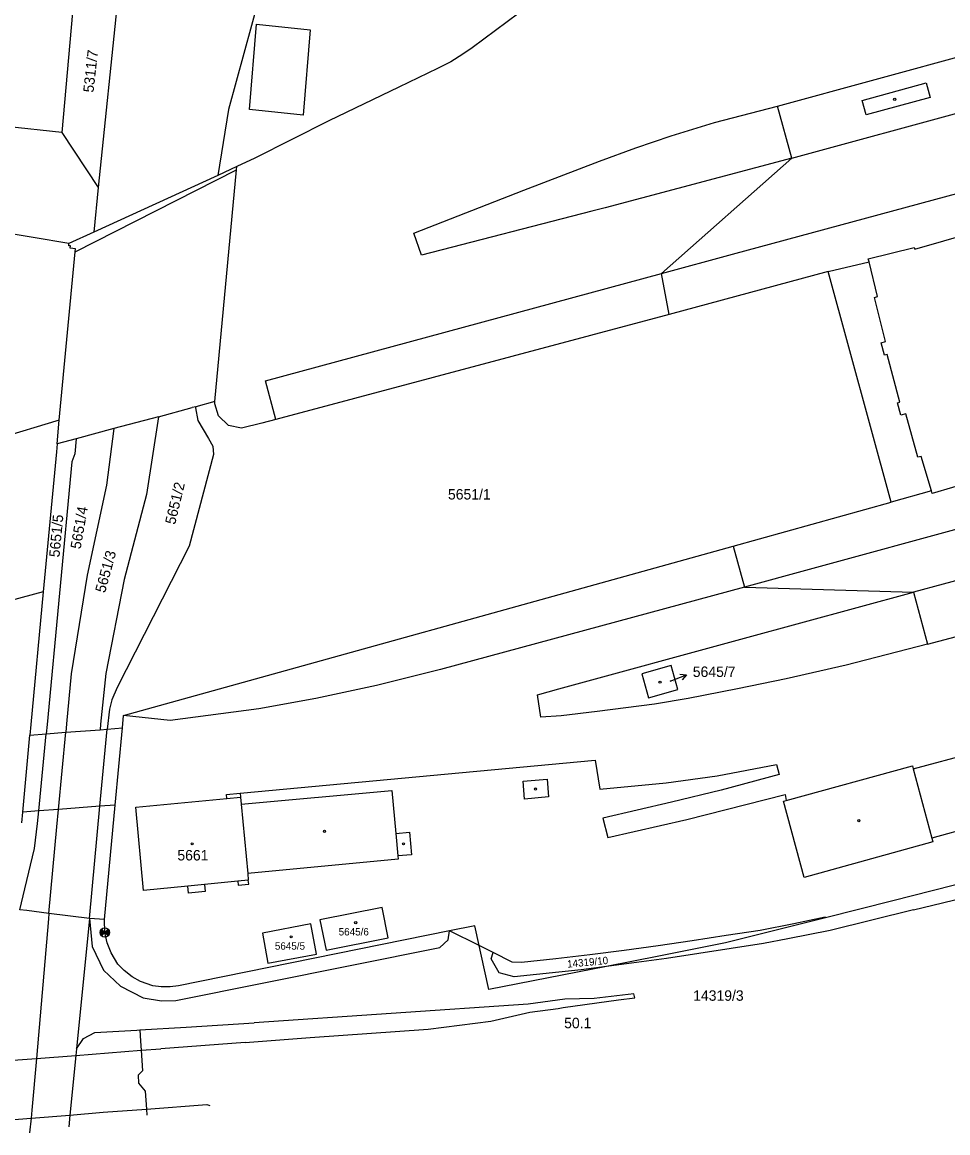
# Model space of a CAD drawing. Extents: x -825057 to -819383, y -1071633 to -1067888.
# Drawn here: x -821893.8 to -821743.3, y -1070405.8 to -1070225.1 of the extents above; entities that cross this region are included whole.
import ezdxf

# ---------------------------------------------------------------- set-up
doc = ezdxf.new("R2010")
doc.units = 0
for name, color, linetype in [('Vrstva 1', 7, 'Continuous'), ('Vrstva 16', 7, 'Continuous'), ('Vrstva 17', 7, 'Continuous'), ('Vrstva 18', 7, 'Continuous'), ('Vrstva 19', 7, 'Continuous'), ('Vrstva 24', 7, 'Continuous'), ('Vrstva 25', 7, 'Continuous'), ('Vrstva 4', 7, 'Continuous')]:
    doc.layers.add(name, color=color, linetype=linetype)

msp = doc.modelspace()

# ---------------------------------------------------------------- linework, layer by layer
at = {"layer": 'Vrstva 1'}
for p, q in [((-821770.97, -1070238.79), (-821656.22, -1070207.49)), ((-821853.88, -1070215.88), (-821860.28, -1070239.36)), ((-821885.09, -1070217.04), (-821887.37, -1070243.06)), ((-821877.85, -1070216.96), (-821881.44, -1070252.03)), ((-821811.14, -1070222.26), (-821820.66, -1070229.3)), ((-821822.14, -1070230.34), (-821824.13, -1070231.61)), ((-821820.66, -1070229.3), (-821822.14, -1070230.34)), ((-821824.13, -1070231.61), (-821826.3, -1070232.65)), ((-821826.3, -1070232.65), (-821832.57, -1070235.71)), ((-821832.57, -1070235.71), (-821843.93, -1070241.18)), ((-821860.28, -1070239.36), (-821862.02, -1070250.06)), ((-821768.65, -1070247.26), (-821770.97, -1070238.79)), ((-821843.93, -1070241.18), (-821856.01, -1070247.24)), ((-821887.37, -1070243.06), (-821881.44, -1070252.03)), ((-821858.9, -1070248.63), (-821862.02, -1070250.06)), ((-821856.01, -1070247.24), (-821858.9, -1070248.63)), ((-821789.86, -1070266.02), (-821768.65, -1070247.26)), ((-821862.02, -1070250.06), (-821882.18, -1070259.28)), ((-821881.44, -1070252.03), (-821882.18, -1070259.28)), ((-821886.25, -1070261.14), (-821912.61, -1070256.71)), ((-821882.18, -1070259.28), (-821886.25, -1070261.14)), ((-821886.26, -1070261.49), (-821886.25, -1070261.14)), ((-821887.79, -1070289.89), (-821885.23, -1070262.51)), ((-821885.97, -1070261.52), (-821886.26, -1070261.49)), ((-821886, -1070261.88), (-821885.97, -1070261.52)), ((-821885.18, -1070262.01), (-821886, -1070261.88)), ((-821885.23, -1070262.51), (-821885.18, -1070262.01)), ((-821788.6, -1070272.7), (-821789.86, -1070266.02)), ((-821762.72, -1070265.7), (-821788.6, -1070272.7)), ((-821752.47, -1070303.19), (-821762.72, -1070265.7)), ((-821788.6, -1070272.7), (-821852.55, -1070289.75)), ((-821871.65, -1070289.3), (-821866.18, -1070287.83)), ((-821865.59, -1070287.68), (-821866.18, -1070287.83)), ((-821865.59, -1070287.68), (-821865.61, -1070287.86)), ((-821865.61, -1070287.86), (-821865.28, -1070289.91)), ((-821862.47, -1070286.84), (-821865.59, -1070287.68)), ((-821862.5, -1070287.2), (-821862.47, -1070286.84)), ((-821861.91, -1070289.16), (-821862.5, -1070287.2)), ((-821887.79, -1070289.89), (-822065.38, -1070343.33)), ((-821888.15, -1070293.72), (-821887.79, -1070289.89)), ((-821871.65, -1070289.3), (-821878.9, -1070291.24)), ((-821871.65, -1070289.3), (-821873.61, -1070301.98)), ((-821865.28, -1070289.91), (-821863.52, -1070292.87)), ((-821860.28, -1070290.72), (-821861.91, -1070289.16)), ((-821852.55, -1070289.75), (-821854.87, -1070290.38)), ((-821878.9, -1070291.24), (-821885.02, -1070292.88)), ((-821878.9, -1070291.24), (-821880.11, -1070300.43)), ((-821858.13, -1070291.19), (-821860.28, -1070290.72)), ((-821854.87, -1070290.38), (-821858.13, -1070291.19)), ((-821888.15, -1070293.72), (-821888.27, -1070294.99)), ((-821885.02, -1070292.88), (-821888.15, -1070293.72)), ((-821885.02, -1070292.88), (-821885.27, -1070295.32)), ((-821863.52, -1070292.87), (-821862.8, -1070294.08)), ((-821888.27, -1070294.99), (-821890.39, -1070317.77)), ((-821885.27, -1070295.32), (-821885.77, -1070296.62)), ((-821862.71, -1070295.46), (-821866.67, -1070310.37)), ((-821862.8, -1070294.08), (-821862.71, -1070295.46)), ((-821885.77, -1070296.62), (-821889.78, -1070339.38)), ((-821880.11, -1070300.43), (-821883.28, -1070315.06)), ((-821873.61, -1070301.98), (-821877.22, -1070315.8)), ((-821778.17, -1070310.34), (-821752.47, -1070303.19)), ((-821866.67, -1070310.37), (-821878.38, -1070333.34)), ((-821877.32, -1070337.92), (-821778.17, -1070310.34)), ((-821778.17, -1070310.34), (-821776.32, -1070317)), ((-821883.28, -1070315.06), (-821885.88, -1070331.13)), ((-821877.22, -1070315.8), (-821880.24, -1070331.05)), ((-821776.32, -1070317), (-821748.88, -1070317.82)), ((-821890.39, -1070317.77), (-821915.8, -1070324.55)), ((-821890.39, -1070317.77), (-821892.42, -1070339.38)), ((-821748.88, -1070317.82), (-821746.56, -1070326.32)), ((-821746.56, -1070326.32), (-821720.29, -1070319.13)), ((-821788.26, -1070329.77), (-821793.05, -1070331.11)), ((-821787.18, -1070333.68), (-821788.26, -1070329.77)), ((-821885.88, -1070331.13), (-821886.6, -1070339.25)), ((-821880.24, -1070331.05), (-821881.06, -1070339.29)), ((-821793.05, -1070331.11), (-821791.97, -1070335.01)), ((-821878.38, -1070333.34), (-821879.27, -1070335.33)), ((-821791.97, -1070335.01), (-821787.18, -1070333.68)), ((-821879.6, -1070336.88), (-821880.02, -1070340.11)), ((-821879.27, -1070335.33), (-821879.6, -1070336.88)), ((-821877.51, -1070339.92), (-821877.32, -1070337.92)), ((-821748.92, -1070346.58), (-821715.23, -1070337.53)), ((-821892.42, -1070339.38), (-821892.57, -1070341.07)), ((-821889.78, -1070339.38), (-821889.92, -1070340.87)), ((-821889.92, -1070340.87), (-821886.73, -1070340.62)), ((-821886.6, -1070339.25), (-821886.73, -1070340.62)), ((-821886.73, -1070340.62), (-821881.14, -1070340.2)), ((-821881.06, -1070339.29), (-821881.14, -1070340.2)), ((-821881.14, -1070340.2), (-821880.02, -1070340.11)), ((-821880.02, -1070340.11), (-821877.51, -1070339.92)), ((-821893.74, -1070353.62), (-821892.57, -1070341.07)), ((-821892.57, -1070341.07), (-821889.92, -1070340.87)), ((-821769.57, -1070351.7), (-821749.05, -1070346.07)), ((-821749.05, -1070346.07), (-821748.92, -1070346.58)), ((-821712.35, -1070348.43), (-821745.89, -1070357.86)), ((-821875.36, -1070352.81), (-821860.52, -1070351.39)), ((-821860.52, -1070351.39), (-821858.31, -1070351.18)), ((-821858.31, -1070351.18), (-821858.2, -1070352.34)), ((-821858.2, -1070352.34), (-821833.72, -1070350.1)), ((-821833.72, -1070350.1), (-821833.07, -1070357.07)), ((-821874.08, -1070366.34), (-821875.36, -1070352.81)), ((-821769.98, -1070351.81), (-821769.57, -1070351.7)), ((-821766.66, -1070364.26), (-821769.98, -1070351.81)), ((-821893.9, -1070355.33), (-821893.74, -1070353.62)), ((-821833.07, -1070357.07), (-821830.82, -1070356.88)), ((-821830.82, -1070356.88), (-821830.5, -1070360.54)), ((-821745.74, -1070358.44), (-821766.66, -1070364.26)), ((-821745.89, -1070357.86), (-821745.74, -1070358.44)), ((-821830.5, -1070360.54), (-821832.73, -1070360.73)), ((-821832.68, -1070361.28), (-821857.15, -1070363.57)), ((-821832.73, -1070360.73), (-821832.68, -1070361.28)), ((-821724.98, -1070361.04), (-821752.21, -1070368.06)), ((-821857.15, -1070363.57), (-821857.05, -1070364.68)), ((-821866.87, -1070365.63), (-821874.08, -1070366.34)), ((-821866.76, -1070366.78), (-821866.87, -1070365.63)), ((-821858.73, -1070364.84), (-821864.19, -1070365.37)), ((-821864.19, -1070365.37), (-821864.08, -1070366.52)), ((-821857.05, -1070364.68), (-821858.73, -1070364.84)), ((-821864.08, -1070366.52), (-821866.76, -1070366.78)), ((-821893.09, -1070369.63), (-821894.23, -1070369.49)), ((-821889.47, -1070370.08), (-821893.09, -1070369.63)), ((-821835.27, -1070369.11), (-821845.4, -1070371.15)), ((-821834.28, -1070374.03), (-821835.27, -1070369.11)), ((-821752.21, -1070368.06), (-821763.16, -1070370.81)), ((-821889.55, -1070370.95), (-821891.51, -1070393.68)), ((-821889.47, -1070370.08), (-821889.55, -1070370.95)), ((-821882.86, -1070370.91), (-821889.47, -1070370.08)), ((-821882.86, -1070370.91), (-821884.99, -1070392.1)), ((-821880.41, -1070371.05), (-821882.86, -1070370.91)), ((-821880.39, -1070373.18), (-821880.41, -1070371.05)), ((-821845.4, -1070371.15), (-821844.41, -1070376.06)), ((-821763.16, -1070370.81), (-821779.44, -1070374.89)), ((-821763.21, -1070370.68), (-821768.35, -1070371.78)), ((-821763.16, -1070370.81), (-821763.21, -1070370.68)), ((-821880, -1070374.86), (-821880.39, -1070373.18)), ((-821824.32, -1070372.91), (-821868.41, -1070381.84)), ((-821846.89, -1070371.77), (-821854.74, -1070373.28)), ((-821845.96, -1070376.71), (-821846.89, -1070371.77)), ((-821820.23, -1070372.08), (-821824.32, -1070372.91)), ((-821819.52, -1070375.3), (-821820.23, -1070372.08)), ((-821773.79, -1070372.85), (-821779.35, -1070373.7)), ((-821768.35, -1070371.78), (-821773.79, -1070372.85)), ((-821879.37, -1070376.51), (-821880, -1070374.86)), ((-821854.74, -1070373.28), (-821853.85, -1070378.19)), ((-821844.41, -1070376.06), (-821834.28, -1070374.03)), ((-821784.88, -1070374.56), (-821790.39, -1070375.37)), ((-821779.44, -1070374.89), (-821790.3, -1070377.03)), ((-821779.35, -1070373.7), (-821784.88, -1070374.56)), ((-821878.26, -1070378.31), (-821879.37, -1070376.51)), ((-821853.85, -1070378.19), (-821845.96, -1070376.71)), ((-821819.24, -1070376.56), (-821819.52, -1070375.3)), ((-821817.21, -1070376.45), (-821819.52, -1070375.3)), ((-821817.94, -1070382.46), (-821819.24, -1070376.56)), ((-821814.12, -1070377.99), (-821817.21, -1070376.45)), ((-821801.48, -1070376.84), (-821807.05, -1070377.47)), ((-821795.92, -1070376.14), (-821801.48, -1070376.84)), ((-821790.39, -1070375.37), (-821795.92, -1070376.14)), ((-821877.22, -1070379.38), (-821878.26, -1070378.31)), ((-821812.62, -1070378.09), (-821814.12, -1070377.99)), ((-821807.05, -1070377.47), (-821812.62, -1070378.09)), ((-821790.3, -1070377.03), (-821798.8, -1070378.7)), ((-821875.96, -1070380.37), (-821877.22, -1070379.38)), ((-821874.56, -1070381.15), (-821875.96, -1070380.37)), ((-821798.8, -1070378.7), (-821817.94, -1070382.46)), ((-821872.57, -1070381.86), (-821874.56, -1070381.15)), ((-821871.2, -1070382.02), (-821872.57, -1070381.86)), ((-821869.74, -1070382.02), (-821871.2, -1070382.02)), ((-821868.41, -1070381.84), (-821869.74, -1070382.02)), ((-821884.99, -1070392.1), (-821885.09, -1070393.18)), ((-821891.51, -1070393.68), (-821892.23, -1070402.09)), ((-821885.09, -1070393.18), (-821886.07, -1070402.87)), ((-821892.23, -1070402.09), (-821892.37, -1070403.39)), ((-821892.37, -1070403.39), (-821892.63, -1070405.76)), ((-821886.07, -1070402.87), (-821886.26, -1070404.8))]:
    msp.add_line(p, q, dxfattribs=at)
at = {"layer": 'Vrstva 16'}
msp.add_line((-821788.45, -1070332.33), (-821785.797, -1070331.289), dxfattribs=at)
msp.add_lwpolyline([(-821786.855, -1070331.194), (-821785.797, -1070331.289), (-821786.508, -1070332.078)], dxfattribs=at)
at = {"layer": 'Vrstva 24'}
for p, q in [((-821881.14, -1070373.18), (-821879.64, -1070373.18)), ((-821881.114, -1070372.986), (-821879.666, -1070373.374)), ((-821881.114, -1070373.374), (-821879.666, -1070372.986)), ((-821881.039, -1070372.805), (-821879.741, -1070373.555)), ((-821881.039, -1070373.555), (-821879.741, -1070372.805)), ((-821880.92, -1070373.71), (-821879.86, -1070372.65)), ((-821880.92, -1070372.65), (-821879.86, -1070373.71))]:
    msp.add_line(p, q, dxfattribs=at)
msp.add_circle((-821880.39, -1070373.18), 0.75, dxfattribs=at)
at = {"layer": 'Vrstva 25'}
for centre in [(-821751.92, -1070237.69), (-821790.08, -1070332.47), (-821810.35, -1070349.85), (-821757.75, -1070355), (-821844.65, -1070356.73), (-821866.17, -1070358.76), (-821831.8, -1070358.77), (-821839.58, -1070371.59), (-821850.08, -1070373.9)]:
    msp.add_circle(centre, 0.175, dxfattribs=at)
at = {"layer": 'Vrstva 4'}
for p, q in [((-821768.65, -1070247.26), (-821655.78, -1070216.48)), ((-821856.88, -1070239.33), (-821855.74, -1070225.48)), ((-821855.74, -1070225.48), (-821847.01, -1070226.39)), ((-821847.01, -1070226.39), (-821848.13, -1070240.26)), ((-821778.29, -1070262.89), (-821655.15, -1070229.56)), ((-821757.21, -1070237.86), (-821746.8, -1070235)), ((-821746.8, -1070235), (-821746.15, -1070237.37)), ((-821746.15, -1070237.37), (-821756.56, -1070240.23)), ((-821848.13, -1070240.26), (-821856.88, -1070239.33)), ((-821781.21, -1070241.47), (-821770.97, -1070238.79)), ((-821756.56, -1070240.23), (-821757.21, -1070237.86)), ((-821887.37, -1070243.06), (-821896.42, -1070242.13)), ((-821788.27, -1070243.61), (-821781.21, -1070241.47)), ((-821794.04, -1070245.6), (-821788.27, -1070243.61)), ((-821799.92, -1070247.74), (-821794.04, -1070245.6)), ((-821858.95, -1070249.13), (-821858.9, -1070248.63)), ((-821812.22, -1070252.44), (-821799.92, -1070247.74)), ((-821768.65, -1070247.26), (-821799, -1070255.31)), ((-821885.23, -1070262.51), (-821858.95, -1070249.13)), ((-821862.47, -1070286.84), (-821858.95, -1070249.13)), ((-821830.12, -1070259.48), (-821812.22, -1070252.44)), ((-821801.15, -1070255.85), (-821828.88, -1070263.02)), ((-821799, -1070255.31), (-821801.15, -1070255.85)), ((-821748.66, -1070262.06), (-821730.49, -1070256.79)), ((-821828.88, -1070263.02), (-821830.12, -1070259.48)), ((-821789.86, -1070266.02), (-821778.29, -1070262.89)), ((-821756.22, -1070263.61), (-821748.73, -1070261.76)), ((-821748.73, -1070261.76), (-821748.66, -1070262.06)), ((-821762.72, -1070265.7), (-821756.09, -1070264.14)), ((-821756.09, -1070264.14), (-821756.22, -1070263.61)), ((-821754.69, -1070269.77), (-821756.09, -1070264.14)), ((-821854.24, -1070283.45), (-821789.86, -1070266.02)), ((-821755.23, -1070269.91), (-821754.69, -1070269.77)), ((-821753.39, -1070277.08), (-821755.23, -1070269.91)), ((-821754.11, -1070277.29), (-821753.39, -1070277.08)), ((-821753.56, -1070279.32), (-821754.11, -1070277.29)), ((-821753.17, -1070279.21), (-821753.56, -1070279.32)), ((-821751.06, -1070286.93), (-821753.17, -1070279.21)), ((-821852.55, -1070289.75), (-821854.24, -1070283.45)), ((-821751.45, -1070287.03), (-821751.06, -1070286.93)), ((-821750.9, -1070289.06), (-821751.45, -1070287.03)), ((-821750.12, -1070288.84), (-821750.9, -1070289.06)), ((-821748.13, -1070295.9), (-821750.12, -1070288.84)), ((-821747.6, -1070295.75), (-821748.13, -1070295.9)), ((-821745.93, -1070301.37), (-821747.6, -1070295.75)), ((-821738.43, -1070299.58), (-821745.81, -1070301.78)), ((-821745.93, -1070301.37), (-821752.47, -1070303.19)), ((-821745.81, -1070301.78), (-821745.93, -1070301.37)), ((-821724.55, -1070302.91), (-821765.81, -1070314.15)), ((-821722.5, -1070310.7), (-821748.88, -1070317.82)), ((-821765.81, -1070314.15), (-821776.32, -1070317)), ((-821776.32, -1070317), (-821825.8, -1070330.44)), ((-821776.32, -1070325.33), (-821748.88, -1070317.82)), ((-821806.54, -1070333.58), (-821776.32, -1070325.33)), ((-821746.56, -1070326.32), (-821759.83, -1070329.69)), ((-821759.83, -1070329.69), (-821769.58, -1070331.93)), ((-821825.8, -1070330.44), (-821836.19, -1070333.04)), ((-821836.19, -1070333.04), (-821846.09, -1070335.14)), ((-821769.58, -1070331.93), (-821777.49, -1070333.57)), ((-821846.09, -1070335.14), (-821855.36, -1070336.82)), ((-821810.01, -1070334.54), (-821806.54, -1070333.58)), ((-821809.46, -1070338.16), (-821810.01, -1070334.54)), ((-821785.51, -1070335.11), (-821791, -1070336.07)), ((-821777.49, -1070333.57), (-821785.51, -1070335.11)), ((-821855.36, -1070336.82), (-821869.74, -1070338.72)), ((-821791, -1070336.07), (-821800.32, -1070337.26)), ((-821869.74, -1070338.72), (-821877.32, -1070337.92)), ((-821806.14, -1070337.96), (-821809.46, -1070338.16)), ((-821800.32, -1070337.26), (-821806.14, -1070337.96)), ((-821887.92, -1070353.18), (-821886.73, -1070340.62)), ((-821881.18, -1070352.66), (-821880.02, -1070340.11)), ((-821878.68, -1070352.47), (-821877.51, -1070339.92)), ((-821891.12, -1070353.42), (-821889.92, -1070340.87)), ((-821858.38, -1070350.54), (-821800.66, -1070345.18)), ((-821800.66, -1070345.18), (-821799.85, -1070349.9)), ((-821780.79, -1070347.72), (-821771.13, -1070345.89)), ((-821771.13, -1070345.89), (-821770.7, -1070347.48)), ((-821789.1, -1070348.84), (-821780.79, -1070347.72)), ((-821770.7, -1070347.48), (-821780.16, -1070350.02)), ((-821748.92, -1070346.58), (-821745.89, -1070357.86)), ((-821812.37, -1070348.6), (-821808.46, -1070348.24)), ((-821812.11, -1070351.49), (-821812.37, -1070348.6)), ((-821808.46, -1070348.24), (-821808.2, -1070351.13)), ((-821799.85, -1070349.9), (-821789.1, -1070348.84)), ((-821860.59, -1070350.75), (-821858.38, -1070350.54)), ((-821860.52, -1070351.39), (-821860.59, -1070350.75)), ((-821858.38, -1070350.54), (-821858.31, -1070351.18)), ((-821808.2, -1070351.13), (-821812.11, -1070351.49)), ((-821780.16, -1070350.02), (-821788.24, -1070351.98)), ((-821785.71, -1070354.82), (-821769.76, -1070350.74)), ((-821769.76, -1070350.74), (-821769.57, -1070351.7)), ((-821887.92, -1070353.18), (-821891.12, -1070353.42)), ((-821888.19, -1070356.02), (-821887.92, -1070353.18)), ((-821881.18, -1070352.66), (-821887.92, -1070353.18)), ((-821882.86, -1070370.91), (-821881.18, -1070352.66)), ((-821878.68, -1070352.47), (-821881.18, -1070352.66)), ((-821880.41, -1070371.05), (-821878.68, -1070352.47)), ((-821858.2, -1070352.34), (-821857.15, -1070363.57)), ((-821788.24, -1070351.98), (-821799.39, -1070354.58)), ((-821891.12, -1070353.42), (-821893.74, -1070353.62)), ((-821891.32, -1070355.46), (-821891.12, -1070353.42)), ((-821799.39, -1070354.58), (-821798.57, -1070357.76)), ((-821798.57, -1070357.76), (-821785.71, -1070354.82)), ((-821891.8, -1070359.51), (-821891.32, -1070355.46)), ((-821889.47, -1070370.08), (-821888.19, -1070356.02)), ((-821833.07, -1070357.07), (-821832.73, -1070360.73)), ((-821893.38, -1070366.1), (-821891.8, -1070359.51)), ((-821864.19, -1070365.37), (-821866.87, -1070365.63)), ((-821858.73, -1070364.84), (-821858.67, -1070365.49)), ((-821858.67, -1070365.49), (-821856.98, -1070365.33)), ((-821856.98, -1070365.33), (-821857.05, -1070364.68)), ((-821894.23, -1070369.49), (-821893.38, -1070366.1)), ((-821748.88, -1070369.49), (-821739.19, -1070367.16)), ((-821748.88, -1070369.49), (-821762.43, -1070372.87)), ((-821882.86, -1070370.91), (-821882.44, -1070375.45)), ((-821824.53, -1070374.38), (-821824.32, -1070372.91)), ((-821819.52, -1070375.3), (-821824.32, -1070372.91)), ((-821762.43, -1070372.87), (-821769.28, -1070374.21)), ((-821825.88, -1070375.63), (-821824.53, -1070374.38)), ((-821773.23, -1070374.98), (-821789.04, -1070377.4)), ((-821769.28, -1070374.21), (-821773.23, -1070374.98)), ((-821882.44, -1070375.45), (-821880.59, -1070379.31)), ((-821868.86, -1070384.25), (-821825.88, -1070375.63)), ((-821817.56, -1070377.48), (-821817.21, -1070376.45)), ((-821816.25, -1070379.72), (-821817.56, -1070377.48)), ((-821789.04, -1070377.4), (-821798.8, -1070378.7)), ((-821880.59, -1070379.31), (-821877.83, -1070381.91)), ((-821813.82, -1070380.4), (-821816.25, -1070379.72)), ((-821802.93, -1070379.25), (-821813.82, -1070380.4)), ((-821798.8, -1070378.7), (-821802.93, -1070379.25)), ((-821877.83, -1070381.91), (-821874.17, -1070383.81)), ((-821874.17, -1070383.81), (-821871.15, -1070384.29)), ((-821805.55, -1070384.05), (-821811.52, -1070384.85)), ((-821800.79, -1070383.93), (-821805.55, -1070384.05)), ((-821794.32, -1070383.15), (-821800.79, -1070383.93)), ((-821796.84, -1070384.15), (-821794.21, -1070383.79)), ((-821794.21, -1070383.79), (-821794.32, -1070383.15)), ((-821871.15, -1070384.29), (-821868.86, -1070384.25)), ((-821811.52, -1070384.85), (-821856.12, -1070387.9)), ((-821811.27, -1070386.12), (-821806.66, -1070385.55)), ((-821806.66, -1070385.55), (-821805.84, -1070385.41)), ((-821805.84, -1070385.41), (-821796.84, -1070384.15)), ((-821827.8, -1070388.9), (-821817.62, -1070387.59)), ((-821817.62, -1070387.59), (-821811.27, -1070386.12)), ((-821883.87, -1070390.44), (-821882.02, -1070389.43)), ((-821882.02, -1070389.43), (-821875.19, -1070389.06)), ((-821875.19, -1070389.06), (-821874.71, -1070389.03)), ((-821874.71, -1070389.03), (-821867.15, -1070388.58)), ((-821874.71, -1070389.03), (-821874.58, -1070390.87)), ((-821867.15, -1070388.58), (-821856.12, -1070387.9)), ((-821846.98, -1070390.26), (-821827.8, -1070388.9)), ((-821884.99, -1070392.1), (-821883.87, -1070390.44)), ((-821874.58, -1070390.87), (-821874.47, -1070392.35)), ((-821857.56, -1070391.06), (-821871.29, -1070392.1)), ((-821857.56, -1070391.06), (-821846.98, -1070390.26)), ((-821885.09, -1070393.18), (-821874.47, -1070392.35)), ((-821874.47, -1070392.35), (-821871.29, -1070392.1)), ((-821874.47, -1070392.35), (-821874.23, -1070395.69)), ((-821896.03, -1070394.03), (-821891.51, -1070393.68)), ((-821891.51, -1070393.68), (-821885.09, -1070393.18)), ((-821874.23, -1070395.69), (-821874.95, -1070396.4)), ((-821874.95, -1070396.4), (-821874.9, -1070397.69)), ((-821874.9, -1070397.69), (-821873.83, -1070398.99)), ((-821873.83, -1070398.99), (-821873.63, -1070401.9)), ((-821880.63, -1070402.43), (-821873.63, -1070401.9)), ((-821873.63, -1070401.9), (-821863.77, -1070401.16)), ((-821873.63, -1070401.9), (-821873.56, -1070402.87)), ((-821863.77, -1070401.16), (-821863.3, -1070401.32)), ((-821898.24, -1070403.87), (-821892.37, -1070403.39)), ((-821892.37, -1070403.39), (-821886.07, -1070402.87)), ((-821886.07, -1070402.87), (-821880.63, -1070402.43))]:
    msp.add_line(p, q, dxfattribs=at)

# ---------------------------------------------------------------- texts
at = {"layer": 'Vrstva 16'}
msp.add_text('5645/7', height=1.7, dxfattribs=at).set_placement((-821784.76, -1070331.63))
at = {"layer": 'Vrstva 17'}
msp.add_text('50.1', height=1.7, dxfattribs=at).set_placement((-821805.682, -1070388.76))
at = {"layer": 'Vrstva 18'}
for s, height, rotation, p in [('5311/7', 1.7, 83.7, (-821882.231, -1070236.657)), ('5651/2', 1.7, 76.5, (-821868.962, -1070306.942)), ('5651/4', 1.7, 80.1, (-821884.327, -1070310.912)), ('5651/5', 1.7, 84.6, (-821887.765, -1070312.219)), ('5651/3', 1.7, 74.7, (-821880.351, -1070318.056)), ('14319/10', 1.2, 5.4, (-821805.14, -1070378.92))]:
    msp.add_text(s, height=height, rotation=rotation, dxfattribs=at).set_placement(p)
for s, p in [('5651/1', (-821824.576, -1070302.77)), ('14319/3', (-821784.7, -1070384.29))]:
    msp.add_text(s, height=1.7, dxfattribs=at).set_placement(p)
at = {"layer": 'Vrstva 19'}
for s, height, p in [('5645/7', 0.2, (-821788.45, -1070332.33)), ('5661', 1.7, (-821868.586, -1070361.47)), ('5645/6', 1.2, (-821842.35, -1070373.67)), ('5645/5', 1.2, (-821852.73, -1070375.98))]:
    msp.add_text(s, height=height, dxfattribs=at).set_placement(p)

doc.saveas('drawing.dxf')
